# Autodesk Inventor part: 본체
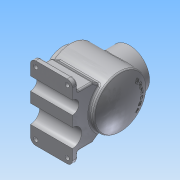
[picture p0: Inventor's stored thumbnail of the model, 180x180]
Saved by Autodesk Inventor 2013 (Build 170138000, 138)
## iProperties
Created: 2018-08
Part Number: 본체
Material: 알루미늄 6061
Document SubType Name: Modeling
Designer: Administrator
Density: 2.71 g/cm^3
Mass: 1886.06 g
Surface Area: 1087.48 cm^2
Volume: 695.962 cm^3
Author: Administrator
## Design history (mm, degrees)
sketch "스케치1"
  geometry: L1 (0, 0)-(326.504, 0); L2 (0, 0)-(0, 38); L3 (0, 38)-(12, 38); L4 (12, 38)-(12, 50); L5 (12, 50)-(108.671, 50); A1 r 116 centre (4, 0) between (120, 0) and (108.671, 50)
  constraints: 10 end point, 3 perpendicular, 2 point on circle, 2 point on line, 1 centre point, 1 horizontal, 1 parallel
  dimensions: "d0" = 76 diameter of L3 L1; "d3" = 100 diameter of L5 L1; "d4" = 116 radius of A1; "d5" = 12 distance between parallel lines of L4 L2; "d6" = 108 horizontal distance of A1.start L4.end
revolve "회전1" sketch "스케치1" stored, may be unused: angle "d7" = 90 deg
feature "쉘1" dims "d8" = 10
sketch "스케치16"
  geometry: C1 r 28 at (0, 0) reference; C2 r 27 at (0, 0); 1 further point
  constraints: 1 centre point, 1 coincident
  dimensions: "d96" = 54 diameter of C2
extrude "돌출6" join sketch "스케치16" distance "d97" = 22; taper "d98" = 0 deg
sketch "스케치3"
  geometry: 2 further points
  constraints: 1 vertical alignment
  dimensions: "d9" = 32.5 distance of point (0, 32.5) point (0, 0)
hole "구멍1" sketch "스케치3" at (0, 32.5) diameter "d10" = 3.242; stored, may be unused: countersink angle "d14" = 90 deg, drill point angle "d16" = 118 deg; dims "d11" = 8, "d12" = 4, "d13" = 2, "d15" = 10
node "작업 평면1"
sketch "스케치4"
  geometry: C1 r 38 at (-62, 0); 1 further point
  constraints: 1 centre point, 1 horizontal alignment
  dimensions: "d21" = 76 diameter of C1; "d22" = 62 distance of C1.centre point (0, 0)
extrude "돌출1" join sketch "스케치4" stored distance "d23" = 10; taper "d24" = 0 deg
hole "구멍2" diameter "d27" = 54; stored, may be unused: countersink angle "d31" = 90 deg, drill point angle "d33" = 118 deg; dims "d25" = 10, "d26" = 10, "d28" = 8, "d29" = 4, "d30" = 2, "d32" = 10
sketch "스케치6"
  geometry: C1 r 27 at (0, 0) reference; 2 further points
  constraints: 1 vertical alignment
  dimensions: "d34" = 32.5 distance of C1.centre point (0, 32.5)
hole "구멍3" sketch "스케치6" at (0, 32.5) diameter "d35" = 3.242; stored, may be unused: countersink angle "d39" = 90 deg, drill point angle "d41" = 118 deg; dims "d36" = 8, "d37" = 4, "d38" = 2, "d40" = 10
node "작업 평면2"
sketch "스케치7"
  geometry: L1 (20, 70)-(100, 70); L2 (100, 70)-(100, -70); L3 (100, -70)-(20, -70); L4 (20, -70)-(20, 70); L5 (12, -50)-(12, 50) reference; C1 r 27 at (62, 0) reference; 3 further points
  constraints: 8 end point, 2 midpoint, 2 parallel, 1 horizontal, 1 horizontal alignment, 1 perpendicular
  dimensions: "d46" = 80 distance of L2.end L3.end; "d47" = 140 distance of L1.end L2.end; "d90" = 8 distance between parallel lines of L4 L5
extrude "돌출2" join sketch "스케치7" distance "d48" = 10; taper "d49" = 0 deg
node "작업 평면3"
sketch "스케치8"
  geometry: L1 (32.496, 38)-(65, 38) reference; L2 (65, 38)-(65, 34.121) reference; L3 (65, 34.121)-(55, 34.121) reference; L4 (55, 34.121)-(54.026, 32.5) reference; L5 (54.026, 32.5)-(55, 30.879) reference; L6 (55, 30.879)-(65, 30.879) reference; L7 (65, 30.879)-(65, 27) reference; L8 (65, 27)-(29.513, 27) reference; L9 (29.513, -27)-(65, -27) reference; L10 (65, -27)-(65, -30.879) reference; L11 (65, -30.879)-(55, -30.879) reference; L12 (55, -30.879)-(54.026, -32.5) reference; L13 (54.026, -32.5)-(55, -34.121) reference; L14 (55, -34.121)-(65, -34.121) reference; L15 (65, -34.121)-(65, -38) reference; L16 (65, -38)-(32.496, -38) reference; L17 (-82, 70)-(-72, 70) reference; L18 (-72, 70)-(-72, -70) reference; L19 (-72, -70)-(-82, -70) reference; L20 (-82, -70)-(-82, 70) reference; L21 (-29.59, -40.304)-(-72, -70); L22 (-29.59, 40.304)-(-72, 70); A1 r 50 centre (0, 0) between (32.496, 38) and (32.496, -38) reference; A2 r 40 centre (0, 0) between (29.513, 27) and (29.513, -27) reference; 1 further point
  constraints: 4 end point, 2 point on circle
  dimensions: "d56" = 35 deg angle of L22 L17; "d57" = 35 deg angle of L19 L21
extrude "돌출3" join sketch "스케치8" distance "d60" = 38; taper "d61" = 0 deg; dims "d91" = 42, "d92" = 0
sketch "스케치9"
  geometry: L1 (0, 0)-(0, 10) reference; L2 (140, 0)-(140, 10) reference; L3 (0, 10)-(20, 10); L4 (20, 10)-(20, 38.563); L5 (29.696, 52.41)-(0, 10) reference; L6 (140, 10)-(110.304, 52.41) reference; L7 (140, 10)-(120, 10); L8 (120, 10)-(120, 38.563); 1 further point
  constraints: 8 end point, 4 perpendicular, 2 point on line
  dimensions: "d62" = 20 distance of L1.end L3.end; "d63" = 20 distance of L2.end L7.end
extrude "돌출4" cut sketch "스케치9" stored distance "d64" = 80; taper "d65" = 0 deg
sketch "스케치10"
  geometry: L1 (0, 0)-(140, 0) reference; L2 (0, 0)-(140, 0); C1 r 12.5 at (42.5, 0); C2 r 17.5 at (92.5, 0); 1 further point
  constraints: 2 centre point, 2 end point, 2 point on line, 1 collinear
  dimensions: "d66" = 25 diameter of C1; "d67" = 17.5 radius of C2; "d68" = 27.5 horizontal distance of C1.centre point (70, 82); "d69" = 22.5 horizontal distance of point (70, 82) C2.centre
extrude "돌출5" cut sketch "스케치10" stored distance "d70" = 80; taper "d71" = 0 deg
fillet "모깎기1" dims "d72" = 10
fillet "모깎기4" dims "d75" = 3
fillet "모깎기2" dims "d73" = 3
fillet "모깎기3" dims "d74" = 3
node "작업 평면4"
sketch "스케치13"
  geometry: C1 r 32.5 at (0, 0); 1 further point
  constraints: 1 centre point, 1 coincident, 1 other
  dimensions: "d80" = 32.5 radius of C1
feature "엠보싱1" sketch "스케치13" dims "d0" = 76, "d3" = 100, "d4" = 116, "d5" = 12, "d6" = 108, "d81" = 0.5, "d82" = 0
sketch "스케치15"
  geometry: A1 r 10 centre (7, -7) between (-3, -7) and (7, -17) reference; A2 r 10 centre (67, -7) between (67, -17) and (77, -7) reference; A3 r 10 centre (67, 113) between (77, 113) and (67, 123) reference; A4 r 10 centre (7, 113) between (7, 123) and (-3, 113) reference; 5 further points
  constraints: 4 coincident
hole "구멍4" sketch "스케치15" at (7, 113), (67, 113), (67, -7), (7, -7) diameter "d83" = 8; stored, may be unused: countersink angle "d87" = 90 deg, drill point angle "d89" = 118 deg; dims "d84" = 8, "d85" = 4, "d86" = 2, "d88" = 10
chamfer "모따기2" distance "d93" = 1; stored, may be unused: second distance "d94" = 2, angle "d95" = 45 deg
chamfer "모따기3" distance "d99" = 1; stored, may be unused: second distance "d100" = 2, angle "d101" = 45 deg
node "솔리드1"
pattern_circular "원형 패턴1" dims angle "d18" = 360 deg
pattern_circular "원형 패턴2" dims angle "d43" = 360 deg
node "절단 모서리 투영1"
other parameters: "d20" = 65, "d45" = -82, "d50" = 62, "d79" = 256
